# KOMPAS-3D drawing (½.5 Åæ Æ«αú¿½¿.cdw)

Views: Вид 1
Referenced files in C:\Program Files\ASCON\KOMPAS-3D V10\Sys\: SPDS.lcs, Graphic.lcs
Referenced files in \\F-server\проектирование\Проекты\РЗА и ПА Тюменские РС\4. Проект\ЭП\Туринская\Рабочая документация\: план располодения оборудования на ПС.cdw
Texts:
  Текст на чертеже
  Размерные надписи
  Шероховатость
  Линия-выноска #1
  Линия-выноска #2
  Линия-выноска #3
  Отклонения формы и база
  Заголовок таблицы
  Ячейка таблицы
  Стрелка вида
  Обозначение изменения
  Фигурная скобка
  Номер узла
  Марка координационной оси
  VRCB
  Выносная надпись
  Обозначение узла
  Марка/позиционное обозначение с линией-выноской
  Марка/позиционное обозначение на линии
  Марка/позиционное обозначение без линии-выноски
  Лит-Масса-Масштаб
  Материал-Предприятие
  Title Specification
  Body Specification ( left align )
  Body Specificaton ( centered )
  Без имени
  Normal
  heading 1
  Знак Знак Знак Знак Знак Знак
  Verdana
  Body Text
  MS Sans Serif
  Txt
  Simplex
  TXT
  Обычный
  Термин
  Список определений
  Адрес
  Цитаты
  Форматированный
  Courier New
  Z-конец формы
  Z-начало формы
  Additional DXF text style 0
  Абзац Знак
  Body Text 3
  Title
  ТекстШаг1
  Шрифт 2.5
  Заголовки
  txt
  heading 2
  AGOpus
  footer
  Денис
  RUSTXT
  Обычный (веб)
  ООббыыччнныыйй
  Definition Term
  Definition List
  Address
  Blockquote
  Preformatted
  z-Bottom of Form
  z-Top of Form
  header
  NormalParagraphStyle
  ссылки
  Подпись в квадратике
  табл
  цепи
  Маркировка
  клеммы, контакты
  тексты табл
  Тексты. 3,2
  ЗОНА_привяз
  текст переноса
  ТТееррммиинн
  ССппииссоокк ооппррееддееллеенниийй
  ААддрреесс
  ЦЦииттааттыы
  ФФооррммааттиирроовваанннныыйй
  Z-ккооннеецц ффооррммыы
  Z-ннааччааллоо ффооррммыы
  GOST 2.304 type A
  rustxt
  heading 8
  heading 3
  heading 6
  heading 7
  russ
  heading 4
  heading 5
  heading 9
  HeliosLight
  Pa3
  Pa1
  Три с половиной
  style2
  Table Contents
  Table Heading
  ГОСТ_МНЕ
  ESK - Обозначение
  маркировка
  ISOCP
  ROMANS
  SIMPLEX
  Текст 3,5
  Tahoma
  CNBNDG+TimesNewRoman
  Subtitle
  FR5
  подписи
  Аппараты
  Ссылки
  Состав чартежа
  ячейка табл.
  Пояснения
  Клеммник текст
  .07 RGB_0_0_0 i0b0u0
  CM12
  romans
  текст табл
  Body Text Indent 3
  Основной текст с отступом 3
  gif
  Пояснения 2
  romanc
  eskd1
  Pa15
  Pa18
  ISOCPEUR
  CC С?т?и?л?ь? П?о? ц?е?н?т?р?у?
  Normal (Web)
  ошиновка 110
  лотки
  Демонтаж
  Монтаж
  Экспликация зданий и сооружений
  Номер
  на плане
  Постоянные здания и сооружения
  ОПУ, совмещенный с ЗРУ 10 кВ
  Существующее
  ЗРУ 10 кВ №1
  Трансформатор 1Т, маслоприемник
  Существующий
  Трансформатор 2Т, маслоприемник
  Трансформатор 3Т, маслоприемник
  Временные здания и сооружения
  III
  Вагон-дом для кратковременного отдых рабочих
  Уборная
  Дизельная электростанция
  Контейнеры для ТБО (0,75м 3 ) и жидких хоз.-быт.стоков(1м 3 )
  «Екатерина» 9,0х3,0
  Туалетная кабина "Люкс"
  ОАО ПКТИпромстрой
  АДС 45-Т400 РЯ
  Примечания:
  1. Для нужд строительства (размещение задействованного в строительстве персонала, обеспечение
  электроэнергией) использовать временные мобильные инвентарные здания;
  2. При выполнении всех строительно-монтажных работ на площадке необходимо руководствоваться
  требованиями СНиП 12-03-2001 "Безопасность труда в строительстве. Общие требования",
  СНиП 12-04-2002 "Безопасность труда в строительстве. Строительное производство", а также
  ПОТ-РМ-016-2001/РД 153-34.0-03.150-00 "Межотраслевые правила по охране труда (правила
  безопасности) при эксплуатации электроустановок";
  3. Наружное освещение строительной площадки осуществляется за счет существующего освещения;
  4. Под временные сооружения (поз. II, III и IV) устраивается площадка из дорожных плит ПД 60-20 на
  щебеночном основании толщиной 15см;
  5. На период строительства для электроснабжения временных зданий и сооружений использовать ди-
  зельную электростанцию. Прокладку  кабеля от дизельной электростанции до вагончиков выполнить
  в воздушном исполнении в гофрированной трубе диаметром 30 мм, на вагончиках кабель закрепить
  скобами. Щиток временного электроснабжения навесить на стенку вагона-дома для отдыха рабочих;
  6. При выполнении монтажных работ использовать инвентарные лестницы и леса;
  7. Условные обозначения см. 16/01-ПОС,л.1.
  8. Тонкой линией изображено существующее оборудование, замена которого проектом не
  предусматривается,  утолщенной - демонтируемое оборудование.
  КМУ ИНМАН ИМ-150
  K5LT_BASIC_RGB_0_0_255_THICK_0.6
  Стили документа
  Бортовой автомобиль КамАЗ 43114-027-02
  АТ ППР#010#0104
  ГИП
  Н.контр.
  Гл.спец.
  Провер.
  Разраб.
  Перезавод ВЛ на ПС Тюмень. Реконструкция устройств
  РЗ и ПА на обратных концах отходящих ВЛ,
  ВОЛС Тюменского ТПО
  ПС 110/10 кВ Торгили
  Матвеев
  Ромин
  Шашерин
  Королева
  Микрюков
  Строительный генеральный план
  Общие технические условия на средний ремонт
Dimensions and other numbers on the sheet: 16/01-ПОД; 7; 2,5; 1,8; 2.5; 3,2_; 3.5; 3,2; 2,5 (контакты, клеммы); 3,2 (надписи); 3,2 (Зоны); 5; 2,5_01; 2,5_3; 3,5_01; 3,5_tabl; 5_заголовок; 2,3_; 3,2_зона не привяз; 3,5; 3.2 маркировка; 3,2 элементы; 3,2 линия; 3,2 таблица; 2,5 грязносинь; 2.5 курсив; 2.5_Э5_надписи; 2.5_Э5_ссылки; 2.5_кабель; 3.2; 2.5 надписи; 3 и 5; 5,0_белый_подчёркнутый; 3.2 фиол; 3.2 (текст); 0 i0b0u0; 1; 2; 3; 4; 6; 11,7; 05.13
